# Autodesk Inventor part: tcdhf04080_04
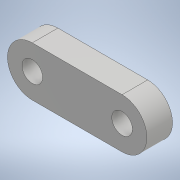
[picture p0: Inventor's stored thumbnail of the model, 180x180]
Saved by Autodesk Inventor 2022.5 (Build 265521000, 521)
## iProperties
Part Number: tcdhf04080_04
Material: 一般
Document SubType Name: Modeling
Designer: ImaoCorp
Density: 1 g/cm^3
Appearance: 既定
Author: ImaoCorp
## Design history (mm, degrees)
feature "tcdhf04080_04"
node "ソリッド1"
